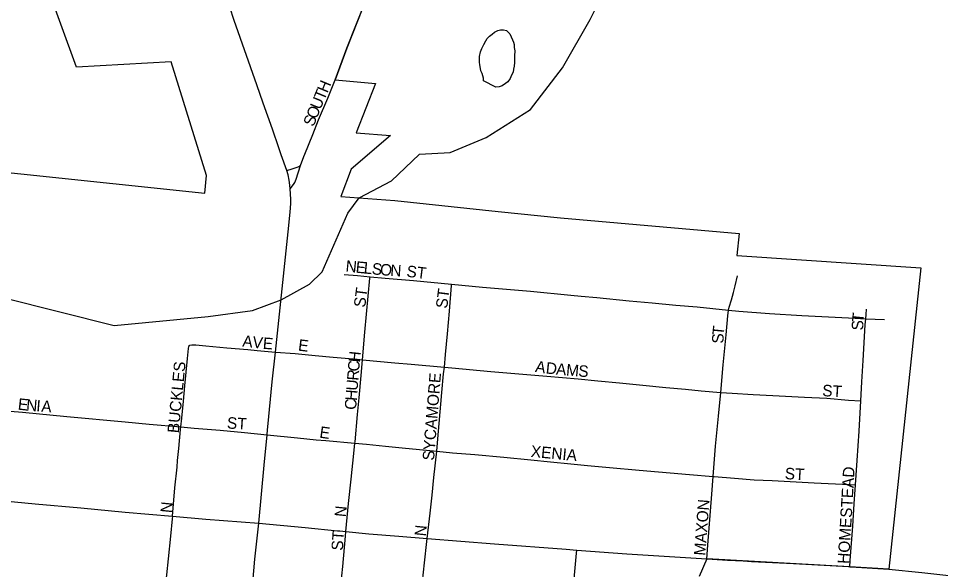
# Model space of a CAD drawing. Extents: x -49 to -8.2, y 9.4 to 23.5.
# Drawn here: x -12.4064 to -12.0269, y 12.6498 to 12.8767 of the extents above; entities that cross this region are included whole.
import ezdxf

# ---------------------------------------------------------------- set-up
doc = ezdxf.new("R2010")
doc.units = 0
for name, color, linetype in [('GM_X_City_Street', 7, 'Continuous'), ('GM_X_City_Street_Text', 7, 'Continuous'), ('GM_X_Corporation', 7, 'Continuous'), ('GM_X_Major_River', 7, 'Continuous'), ('GM_X_Minor_Lake', 7, 'Continuous'), ('GM_X_State_Route', 7, 'Continuous')]:
    doc.layers.add(name, color=color, linetype=linetype)

msp = doc.modelspace()

# ---------------------------------------------------------------- linework, layer by layer
at = {"layer": 'GM_X_City_Street'}
for points in [[(-12.28853, 12.82082), (-12.28529, 12.82893), (-12.28287, 12.83494), (-12.27912, 12.8438), (-12.27607, 12.85138), (-12.27128, 12.86448), (-12.26303, 12.88527), (-12.25356, 12.9095), (-12.24733, 12.92531), (-12.23813, 12.94872), (-12.22985, 12.96944)], [(-12.29025, 12.81613), (-12.28891, 12.81989), (-12.28853, 12.82082)], [(-12.29587, 12.81414), (-12.29372, 12.81476), (-12.29248, 12.81512), (-12.2913, 12.81565), (-12.29025, 12.81613)], [(-12.29455, 12.80646), (-12.29322, 12.80832), (-12.29269, 12.8092), (-12.29216, 12.81053), (-12.29025, 12.81613)], [(-12.27236, 12.77129), (-12.26685, 12.7708), (-12.2617, 12.77035)], [(-12.2648, 12.73615), (-12.26381, 12.7475), (-12.26175, 12.76973), (-12.2617, 12.77035)], [(-12.2617, 12.77035), (-12.25551, 12.76981), (-12.24377, 12.76876), (-12.2281, 12.76728)], [(-12.11415, 12.75663), (-12.11386, 12.75776), (-12.11292, 12.76089), (-12.11209, 12.76382), (-12.11143, 12.76659), (-12.1105, 12.77068)], [(-12.23111, 12.73304), (-12.23057, 12.73833), (-12.22983, 12.74679), (-12.22901, 12.7561), (-12.22815, 12.76669), (-12.2281, 12.76728)], [(-12.2281, 12.76728), (-12.21538, 12.76609), (-12.1957, 12.76434), (-12.17906, 12.76273), (-12.17481, 12.76233), (-12.16842, 12.76175), (-12.15506, 12.76045), (-12.14564, 12.75953), (-12.13582, 12.75866), (-12.12711, 12.75789), (-12.11415, 12.75663)], [(-12.11735, 12.72265), (-12.11634, 12.73403), (-12.11519, 12.74645), (-12.11447, 12.75418), (-12.11415, 12.75663)], [(-12.11415, 12.75663), (-12.10985, 12.75621), (-12.09729, 12.75515), (-12.08396, 12.75441), (-12.07027, 12.75371), (-12.062, 12.75328), (-12.05771, 12.75306)], [(-12.05771, 12.75306), (-12.05757, 12.75484), (-12.0574, 12.75699)], [(-12.05969, 12.71925), (-12.05925, 12.72713), (-12.05875, 12.73582), (-12.05791, 12.7505), (-12.05771, 12.75306)], [(-12.05771, 12.75306), (-12.04999, 12.75266)], [(-12.33955, 12.70849), (-12.33921, 12.71206), (-12.33851, 12.71917), (-12.33793, 12.72547), (-12.33676, 12.73663), (-12.33635, 12.74081), (-12.33627, 12.74155), (-12.33616, 12.74181), (-12.33606, 12.742), (-12.33579, 12.74221), (-12.33509, 12.74233), (-12.33427, 12.74235), (-12.33343, 12.74229), (-12.32924, 12.7419), (-12.32068, 12.74112), (-12.31196, 12.74032), (-12.30821, 12.73999), (-12.30365, 12.73958), (-12.30062, 12.73931)], [(-12.30062, 12.73931), (-12.29246, 12.73869), (-12.28424, 12.7379), (-12.27682, 12.73723), (-12.26696, 12.73635), (-12.2648, 12.73615)], [(-12.26792, 12.70187), (-12.26788, 12.70232), (-12.26687, 12.71357), (-12.26623, 12.72049), (-12.26537, 12.72961), (-12.2648, 12.73615)], [(-12.2648, 12.73615), (-12.25151, 12.73491), (-12.24478, 12.73429), (-12.23111, 12.73304)], [(-12.23426, 12.69854), (-12.23395, 12.70192), (-12.2321, 12.72263), (-12.23139, 12.73035), (-12.23111, 12.73304)], [(-12.23111, 12.73304), (-12.22807, 12.73276), (-12.21203, 12.73129), (-12.1889, 12.72936), (-12.17599, 12.72828), (-12.16795, 12.72749), (-12.15906, 12.72662), (-12.14945, 12.72567), (-12.13995, 12.72479), (-12.13184, 12.72402), (-12.12544, 12.72342), (-12.11735, 12.72265)], [(-12.12046, 12.68808), (-12.11948, 12.70062), (-12.11822, 12.71299), (-12.11735, 12.72265)], [(-12.11735, 12.72265), (-12.11265, 12.72236), (-12.10397, 12.72186), (-12.09596, 12.72145), (-12.08294, 12.72077), (-12.07369, 12.72029), (-12.06478, 12.71956), (-12.05969, 12.71925)], [(-12.45421, 12.7185), (-12.44348, 12.71765), (-12.43646, 12.71709), (-12.42684, 12.71632), (-12.40474, 12.71456), (-12.38648, 12.71282), (-12.36246, 12.71055), (-12.35256, 12.70966), (-12.33955, 12.70849)], [(-12.06194, 12.68464), (-12.06124, 12.69474), (-12.0604, 12.70674), (-12.05969, 12.71925)], [(-12.34303, 12.67177), (-12.34198, 12.68338), (-12.3411, 12.69199), (-12.34087, 12.69472), (-12.34042, 12.69958), (-12.33965, 12.7075), (-12.33955, 12.70849)], [(-12.33955, 12.70849), (-12.33405, 12.708), (-12.32333, 12.7071), (-12.31342, 12.70625), (-12.30408, 12.7053)], [(-12.30408, 12.7053), (-12.29156, 12.70398), (-12.28393, 12.7032), (-12.27995, 12.7029), (-12.26792, 12.70187)], [(-12.2716, 12.66542), (-12.27056, 12.67697), (-12.26951, 12.68695), (-12.26838, 12.69757), (-12.26792, 12.70187)], [(-12.26792, 12.70187), (-12.26311, 12.70146), (-12.25529, 12.70061), (-12.24849, 12.69995), (-12.23426, 12.69854)], [(-12.23817, 12.66254), (-12.23696, 12.67299), (-12.23617, 12.68046), (-12.23542, 12.68767), (-12.23426, 12.69854)], [(-12.23426, 12.69854), (-12.22772, 12.6979), (-12.21862, 12.69709), (-12.20661, 12.696), (-12.19558, 12.69494), (-12.18743, 12.69415), (-12.17907, 12.69334), (-12.17216, 12.69267), (-12.16318, 12.69181), (-12.15095, 12.69063), (-12.13024, 12.68888), (-12.12046, 12.68808)], [(-12.1231, 12.65421), (-12.12274, 12.65975), (-12.12103, 12.68081), (-12.12046, 12.68808)], [(-12.12046, 12.68808), (-12.12004, 12.68805), (-12.11168, 12.68738), (-12.10365, 12.68678), (-12.09623, 12.68639), (-12.08384, 12.6858), (-12.07889, 12.68546), (-12.06431, 12.68476), (-12.06194, 12.68464)], [(-12.06422, 12.65095), (-12.06404, 12.65351), (-12.06306, 12.66769), (-12.06249, 12.6768), (-12.06194, 12.68464)], [(-12.45735, 12.68228), (-12.44831, 12.68144), (-12.43752, 12.68043), (-12.41805, 12.67857), (-12.39952, 12.67684), (-12.38074, 12.6752), (-12.36251, 12.67346), (-12.34303, 12.67177)], [(-12.34303, 12.67177), (-12.34314, 12.67071), (-12.34387, 12.66346), (-12.34479, 12.65414), (-12.34548, 12.64757), (-12.34591, 12.64356), (-12.34619, 12.64047), (-12.34631, 12.6383), (-12.34627, 12.6376), (-12.34619, 12.63713), (-12.34598, 12.63672), (-12.34574, 12.63641), (-12.34543, 12.63612), (-12.34506, 12.63591), (-12.34458, 12.63579), (-12.34378, 12.63569), (-12.34082, 12.63549), (-12.33591, 12.63515), (-12.33064, 12.6348), (-12.32374, 12.63433), (-12.31084, 12.63323)], [(-12.34303, 12.67177), (-12.32925, 12.67057), (-12.30739, 12.6689)], [(-12.27519, 12.63011), (-12.27418, 12.63952), (-12.27293, 12.65105), (-12.27178, 12.66351), (-12.2716, 12.66542)], [(-12.24181, 12.62745), (-12.2414, 12.63097), (-12.24086, 12.63656), (-12.24006, 12.64489), (-12.23931, 12.65254), (-12.23831, 12.66129), (-12.23817, 12.66254)], [(-12.18162, 12.60937), (-12.18108, 12.61416), (-12.18063, 12.61828), (-12.17978, 12.62661), (-12.17895, 12.63463), (-12.17767, 12.64592), (-12.17673, 12.65653), (-12.17661, 12.65781)]]:
    msp.add_lwpolyline(points, dxfattribs=at)
at = {"layer": 'GM_X_Corporation'}
for points in [[(-12.44338, 12.81664), (-12.32967, 12.8047), (-12.32904, 12.81202), (-12.34352, 12.8588), (-12.38255, 12.8566), (-12.40714, 12.9245)], [(-12.25428, 12.90766), (-12.27128, 12.86448), (-12.27607, 12.85138), (-12.25951, 12.84989), (-12.26746, 12.82965), (-12.25322, 12.82853), (-12.26941, 12.81463), (-12.27376, 12.80342), (-12.25155, 12.80166), (-12.20899, 12.79726), (-12.18326, 12.7946), (-12.10981, 12.78816), (-12.11074, 12.77908), (-12.03498, 12.77401), (-12.04813, 12.65), (-12.06422, 12.65095), (-12.1231, 12.65421), (-12.12624, 12.64695)]]:
    msp.add_lwpolyline(points, dxfattribs=at)
at = {"layer": 'GM_X_Major_River'}
msp.add_lwpolyline([(-12.41233, 12.7616), (-12.36697, 12.75024), (-12.3283, 12.75401), (-12.31009, 12.75649), (-12.29828, 12.76081), (-12.28661, 12.76721), (-12.2814, 12.77242), (-12.27089, 12.79651), (-12.26623, 12.80286), (-12.25285, 12.8098), (-12.24725, 12.8152), (-12.24128, 12.82077), (-12.22878, 12.82146), (-12.2139, 12.82762), (-12.1957, 12.83921), (-12.18249, 12.8564), (-12.17112, 12.87629), (-12.12659, 12.96536)], dxfattribs=at)
at = {"layer": 'GM_X_Minor_Lake'}
msp.add_lwpolyline([(-12.21501, 12.85093), (-12.215, 12.85207), (-12.21555, 12.85398), (-12.2161, 12.85512), (-12.21628, 12.85608), (-12.21646, 12.8576), (-12.21663, 12.85874), (-12.21662, 12.86007), (-12.21661, 12.86102), (-12.21621, 12.86292), (-12.21563, 12.86424), (-12.21485, 12.86594), (-12.21408, 12.86745), (-12.2135, 12.86839), (-12.21254, 12.86933), (-12.21139, 12.87027), (-12.21043, 12.87102), (-12.2091, 12.87177), (-12.20796, 12.87194), (-12.20682, 12.87193), (-12.20549, 12.87173), (-12.20418, 12.87038), (-12.20307, 12.8679), (-12.2027, 12.86694), (-12.20233, 12.86599), (-12.20234, 12.86466), (-12.20217, 12.86333), (-12.20219, 12.86124), (-12.20222, 12.85858), (-12.20242, 12.85706), (-12.20263, 12.85573), (-12.20283, 12.8546), (-12.20341, 12.85327), (-12.204, 12.85195), (-12.20496, 12.85063), (-12.20592, 12.84988), (-12.20725, 12.84895), (-12.20858, 12.84858), (-12.20991, 12.84841), (-12.21501, 12.85093)], dxfattribs=at)
at = {"layer": 'GM_X_State_Route'}
for points in [[(-12.29474, 12.80801), (-12.29499, 12.81009), (-12.29541, 12.81227), (-12.29587, 12.81414), (-12.2982, 12.82052), (-12.29919, 12.82341), (-12.30178, 12.83112), (-12.30567, 12.84182), (-12.30828, 12.84934), (-12.31756, 12.87583), (-12.31936, 12.88132)], [(-12.30392, 12.70728), (-12.30381, 12.70858), (-12.30193, 12.72701), (-12.30062, 12.73931), (-12.29534, 12.78879), (-12.29459, 12.79698), (-12.29434, 12.80053), (-12.29426, 12.80229), (-12.29455, 12.80646), (-12.29474, 12.80801)], [(-12.30739, 12.6689), (-12.3053, 12.69275), (-12.30408, 12.7053), (-12.30392, 12.70728)], [(-12.31355, 12.60669), (-12.31144, 12.62601), (-12.31084, 12.63323), (-12.30908, 12.65408), (-12.30739, 12.6689)], [(-12.30739, 12.6689), (-12.28839, 12.66703), (-12.27512, 12.66575), (-12.27409, 12.66565)], [(-12.27409, 12.66565), (-12.2716, 12.66542), (-12.26214, 12.66455), (-12.24985, 12.66348), (-12.23817, 12.66254), (-12.22427, 12.66143)], [(-12.22427, 12.66143), (-12.21047, 12.66033), (-12.18104, 12.65814), (-12.17661, 12.65781), (-12.15597, 12.65626), (-12.1231, 12.65421)], [(-12.1231, 12.65421), (-12.11462, 12.6537)], [(-12.11462, 12.6537), (-12.10819, 12.65331), (-12.10464, 12.65313)], [(-12.10464, 12.65313), (-12.08738, 12.65226), (-12.06472, 12.65097)], [(-12.06472, 12.65097), (-12.06422, 12.65095), (-12.06377, 12.65092), (-12.04813, 12.65), (-12.03457, 12.64855), (-12.00368, 12.64517), (-11.98639, 12.64327), (-11.97219, 12.64158), (-11.96049, 12.63998), (-11.95423, 12.63913), (-11.95034, 12.63824), (-11.94644, 12.63718), (-11.94281, 12.63594), (-11.93988, 12.63479), (-11.93741, 12.63372), (-11.93501, 12.63257), (-11.93307, 12.63151)]]:
    msp.add_lwpolyline(points, dxfattribs=at)

# ---------------------------------------------------------------- texts
at = {"layer": 'GM_X_City_Street_Text'}
for s, height, rotation, p in [('H', 0.00473, 67.3667, (-12.27928, 12.84573)), ('T', 0.00473, 67.3717, (-12.28057, 12.84266)), ('U', 0.00473, 67.3869, (-12.28217, 12.83881)), ('O', 0.00473, 67.8374, (-12.28374, 12.83496)), ('S', 0.00473, 69.0762, (-12.28492, 12.83187)), ('N', 0.00473, 354.3068, (-12.27191, 12.77245)), ('E', 0.00473, 354.3084, (-12.26776, 12.77204)), ('L', 0.00473, 354.2813, (-12.26444, 12.77171)), ('S', 0.00473, 354.3007, (-12.26112, 12.77138)), ('O', 0.00473, 355.139, (-12.25773, 12.77104)), ('N', 0.00473, 356.3782, (-12.25347, 12.77068)), ('ST', 0.004735, 352.88, (-12.24689, 12.77037)), ('ST', 0.004735, 82.8783, (-12.26371, 12.75751)), ('ST', 0.004735, 82.8783, (-12.22996, 12.75709)), ('T', 0.00473, 84.2812, (-12.05867, 12.75144)), ('S', 0.00473, 89.0438, (-12.05872, 12.74821)), ('T', 0.00473, 84.2269, (-12.11616, 12.74602)), ('A', 0.00473, 353.626, (-12.31439, 12.74162)), ('V', 0.00473, 353.626, (-12.31025, 12.74116)), ('E', 0.00473, 355.4159, (-12.30595, 12.74068)), ('E', 0.00473, 352.8783, (-12.29147, 12.73995)), ('S', 0.00473, 88.8799, (-12.11622, 12.74279)), ('H', 0.00473, 83.9567, (-12.26589, 12.73488)), ('BUCKLES', 0.004735, 84.5223, (-12.34039, 12.70579)), ('C', 0.00473, 85.3573, (-12.26619, 12.73117)), ('A', 0.00473, 351.0012, (-12.19392, 12.73119)), ('D', 0.00473, 354.0337, (-12.18953, 12.73051)), ('A', 0.00473, 355.2182, (-12.18528, 12.73006)), ('M', 0.00473, 355.2507, (-12.18113, 12.72971)), ('S', 0.00473, 355.2533, (-12.17614, 12.7293)), ('R', 0.00473, 85.3648, (-12.26649, 12.72743)), ('SYCAMORE', 0.004735, 85.348, (-12.23539, 12.6945)), ('U', 0.00473, 85.3616, (-12.26683, 12.72328)), ('ST', 0.004735, 356.4254, (-12.07569, 12.72121)), ('H', 0.00473, 85.3531, (-12.26716, 12.71912)), ('E', 0.00473, 353.7263, (-12.4068, 12.71564)), ('N', 0.00473, 355.3531, (-12.40334, 12.71526)), ('I', 0.00473, 355.4504, (-12.39918, 12.71493)), ('A', 0.00473, 355.4881, (-12.3971, 12.71476)), ('C', 0.00473, 85.3573, (-12.26747, 12.71539)), ('ST', 0.004735, 356.4254, (-12.32069, 12.70787)), ('E', 0.00473, 351.8743, (-12.2827, 12.70411)), ('XENIA', 0.004735, 354.6138, (-12.19566, 12.6962)), ('ST', 0.004735, 356.4262, (-12.09111, 12.68704)), ('HOMESTEAD', 0.004735, 86.6723, (-12.06455, 12.65202)), ('N', 0.00473, 84.2699, (-12.3433, 12.67291)), ('N', 0.00473, 84.2916, (-12.27163, 12.67124)), ('MAXON', 0.004735, 85.5997, (-12.12372, 12.65538)), ('N', 0.00473, 84.2937, (-12.23871, 12.66332)), ('ST', 0.004735, 86.1879, (-12.27289, 12.65746))]:
    msp.add_text(s, height=height, rotation=rotation, dxfattribs=at).set_placement(p)

doc.saveas('drawing.dxf')
